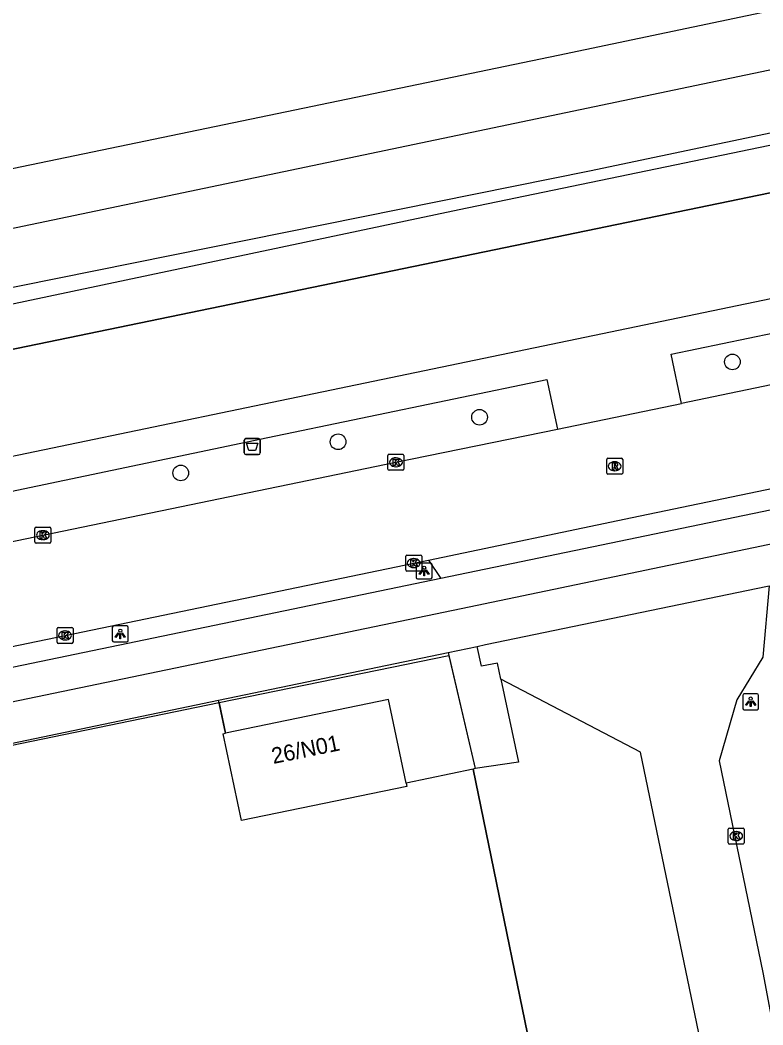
# Model space of a CAD drawing. Extents: x 164494 to 166241, y 382475 to 384494.
# Drawn here: x 164884.7 to 164931.2, y 384302.2 to 384365.1 of the extents above; entities that cross this region are included whole.
import ezdxf

# ---------------------------------------------------------------- set-up
doc = ezdxf.new("R2010")
doc.units = 0
for name, color, linetype in [('IMGEO_Afvalbak', 7, 'Continuous'), ('IMGEO_Boom', 7, 'Continuous'), ('IMGEO_Fietspad_open', 7, 'Continuous'), ('IMGEO_Greppel_droge_sloot', 7, 'Continuous'), ('IMGEO_Groenvoorziening', 7, 'Continuous'), ('IMGEO_Hek', 7, 'Continuous'), ('IMGEO_Kolk', 7, 'Continuous'), ('IMGEO_Lichtpunt', 7, 'Continuous'), ('IMGEO_Pand', 7, 'Continuous'), ('IMGEO_Pand_nummerreeks', 7, 'Continuous'), ('IMGEO_Rijbaan_lokaal_open', 7, 'Continuous'), ('IMGEO_Rioolput', 7, 'Continuous'), ('IMGEO_Spoor', 7, 'Continuous'), ('IMGEO_Spoorbaan_halfverhard', 7, 'Continuous'), ('IMGEO_Voetpad_open', 7, 'Continuous')]:
    doc.layers.add(name, color=color, linetype=linetype)

msp = doc.modelspace()

# ---------------------------------------------------------------- linework, layer by layer
at = {"layer": 'IMGEO_Afvalbak'}
for p, q in [((164898.756, 384338.007), (164898.756, 384338.807)), ((164898.756, 384338.807), (164898.756, 384338.007)), ((164898.856, 384338.907), (164899.646, 384338.907)), ((164899.646, 384338.907), (164898.856, 384338.907)), ((164899.746, 384338.807), (164899.746, 384338.007)), ((164899.746, 384338.007), (164899.746, 384338.807)), ((164899.646, 384337.907), (164898.856, 384337.907)), ((164898.856, 384337.907), (164899.646, 384337.907))]:
    msp.add_line(p, q, dxfattribs=at)
msp.add_lwpolyline([(164898.899, 384338.621), (164899.603, 384338.621), (164899.454, 384338.151), (164899.048, 384338.151), (164898.899, 384338.621)], dxfattribs=at)
for centre, start, end in [((164898.856, 384338.807), 90, 180), ((164898.856, 384338.807), 90, 180), ((164899.646, 384338.807), 0, 90), ((164899.646, 384338.807), 360, 90), ((164898.856, 384338.007), 180, 270), ((164898.856, 384338.007), 180, 270), ((164899.646, 384338.007), 270, 0), ((164899.646, 384338.007), 270, 0)]:
    msp.add_arc(centre, 0.1, start, end, dxfattribs=at)
at = {"layer": 'IMGEO_Boom'}
for centre in [(164929.289, 384343.703), (164913.47, 384340.242), (164904.622, 384338.703), (164894.777, 384336.754)]:
    msp.add_circle(centre, 0.489, dxfattribs=at)
at = {"layer": 'IMGEO_Fietspad_open'}
for points in [[(164926.103, 384341.106), (164925.461, 384344.192), (164936.708, 384346.52), (164998.737, 384359.434), (165044.842, 384369.066), (165078.417, 384376.067), (165103.145, 384381.247)], [(165123.59, 384372.323), (165118.614, 384371.278), (165101.155, 384367.679), (165052.181, 384357.436), (165001.876, 384346.919), (164996.584, 384345.814), (164978.743, 384342.085), (164958.923, 384337.938), (164932.507, 384332.46), (164912.329, 384328.255), (164868.92, 384319.253), (164838.611, 384312.969), (164833.08, 384311.822), (164809.925, 384307.04), (164802.068, 384305.407)], [(164984.803, 384358.696), (164934.915, 384348.321), (164898.89, 384340.836), (164875.602, 384335.981), (164845.275, 384329.624), (164797.88, 384319.828), (164794.806, 384319.188)], [(164795.6, 384317.184), (164798.561, 384317.801), (164845.552, 384327.536), (164876.06, 384333.902), (164900.22, 384338.981), (164917.673, 384342.602), (164918.341, 384339.504)], [(164911.059, 384330.145), (164868.55, 384321.331), (164832.678, 384313.85)]]:
    msp.add_lwpolyline(points, dxfattribs=at)
at = {"layer": 'IMGEO_Greppel_droge_sloot'}
for points in [[(165104.993, 384388.454), (165106.065, 384389.82), (165106.003, 384390.697), (165105.583, 384391.703), (165104.253, 384391.797), (165094.853, 384389.829), (165092.786, 384389.521), (165090.64, 384389.08), (165088.711, 384388.988), (165086.738, 384389.38), (165085.335, 384389.341), (165083.775, 384389.121), (165040.998, 384380.02), (165000.91, 384371.603), (164912.198, 384353.222), (164815.807, 384332.872), (164812.064, 384331.961), (164811.065, 384331.621), (164810.561, 384331.362), (164810.234, 384331.045), (164809.929, 384330.437), (164809.818, 384329.948), (164809.989, 384329.284), (164810.161, 384329.041)], [(164983.603, 384364.664), (164950.027, 384358.074), (164862.281, 384339.951), (164810.161, 384329.041)]]:
    msp.add_lwpolyline(points, dxfattribs=at)
at = {"layer": 'IMGEO_Groenvoorziening'}
msp.add_lwpolyline([(164930.87, 384284.21), (164924.878, 384283.015), (164922.096, 384296.28), (164917.769, 384295.38), (164913.081, 384318.227)], dxfattribs=at)
at = {"layer": 'IMGEO_Hek'}
for points in [[(164792.371, 384325.328), (164793.82, 384325.659), (164799.547, 384326.819), (164862.281, 384339.951), (164950.027, 384358.074), (164999.896, 384367.862), (165017.437, 384370.613), (165038.566, 384374.957), (165060.537, 384379.313), (165104.993, 384388.454), (165107.365, 384388.949), (165107.179, 384392.936), (165107.536, 384394.767)], [(164911.555, 384325.324), (164897.184, 384322.369)], [(164911.555, 384325.324), (164913.199, 384318.262)], [(164897.184, 384322.369), (164884.739, 384319.811), (164842.119, 384310.96), (164840.566, 384310.552)], [(164897.184, 384322.369), (164897.584, 384320.476)], [(164913.081, 384318.227), (164908.88, 384317.354)], [(164913.199, 384318.262), (164913.081, 384318.227)], [(164913.081, 384318.227), (164917.769, 384295.38)]]:
    msp.add_lwpolyline(points, dxfattribs=at)
at = {"layer": 'IMGEO_Kolk'}
for p, q in [((164907.741, 384336.994), (164907.741, 384337.846)), ((164907.816, 384337.92), (164908.668, 384337.92)), ((164908.229, 384337.7), (164908.254, 384337.7)), ((164908.742, 384337.846), (164908.742, 384336.994)), ((164908.252, 384337.14), (164908.227, 384337.14)), ((164908.668, 384336.92), (164907.816, 384336.92)), ((164885.654, 384332.436), (164885.654, 384333.288)), ((164885.729, 384333.362), (164886.581, 384333.362)), ((164886.655, 384333.288), (164886.655, 384332.436)), ((164886.142, 384333.142), (164886.167, 384333.142)), ((164886.581, 384332.362), (164885.729, 384332.362)), ((164886.165, 384332.582), (164886.14, 384332.582)), ((164908.852, 384330.69), (164908.852, 384331.542)), ((164908.927, 384331.616), (164909.779, 384331.616)), ((164909.853, 384331.542), (164909.853, 384330.69)), ((164909.363, 384330.836), (164909.338, 384330.836)), ((164909.34, 384331.396), (164909.365, 384331.396)), ((164909.779, 384330.616), (164908.927, 384330.616)), ((164887.038, 384326.164), (164887.038, 384327.016)), ((164887.113, 384327.09), (164887.965, 384327.09)), ((164888.039, 384327.016), (164888.039, 384326.164)), ((164887.526, 384326.87), (164887.551, 384326.87)), ((164887.965, 384326.09), (164887.113, 384326.09)), ((164887.549, 384326.31), (164887.524, 384326.31)), ((164929.029, 384313.618), (164929.029, 384314.47)), ((164929.104, 384314.544), (164929.956, 384314.544)), ((164930.03, 384314.47), (164930.03, 384313.618)), ((164929.517, 384314.324), (164929.542, 384314.324)), ((164929.956, 384313.544), (164929.104, 384313.544)), ((164929.54, 384313.764), (164929.515, 384313.764))]:
    msp.add_line(p, q, dxfattribs=at)
for points in [[(164907.741, 384336.994), (164907.741, 384337.846)], [(164907.816, 384337.92), (164908.668, 384337.92)], [(164908.742, 384337.846), (164908.742, 384336.994)], [(164908.062, 384337.62), (164908.185, 384337.62), (164908.185, 384337.469), (164908.315, 384337.62), (164908.479, 384337.62), (164908.333, 384337.469), (164908.486, 384337.22), (164908.334, 384337.22), (164908.249, 384337.384), (164908.185, 384337.317), (164908.185, 384337.22), (164908.062, 384337.22), (164908.062, 384337.62)], [(164908.668, 384336.92), (164907.816, 384336.92)], [(164885.654, 384332.436), (164885.654, 384333.288)], [(164885.729, 384333.362), (164886.581, 384333.362)], [(164886.655, 384333.288), (164886.655, 384332.436)], [(164885.975, 384333.062), (164886.098, 384333.062), (164886.098, 384332.911), (164886.228, 384333.062), (164886.392, 384333.062), (164886.246, 384332.911), (164886.399, 384332.662), (164886.247, 384332.662), (164886.162, 384332.826), (164886.098, 384332.759), (164886.098, 384332.662), (164885.975, 384332.662), (164885.975, 384333.062)], [(164886.581, 384332.362), (164885.729, 384332.362)], [(164908.852, 384330.69), (164908.852, 384331.542)], [(164908.927, 384331.616), (164909.779, 384331.616)], [(164909.853, 384331.542), (164909.853, 384330.69)], [(164909.173, 384331.316), (164909.296, 384331.316), (164909.296, 384331.165), (164909.426, 384331.316), (164909.59, 384331.316), (164909.444, 384331.165), (164909.597, 384330.916), (164909.445, 384330.916), (164909.36, 384331.08), (164909.296, 384331.013), (164909.296, 384330.916), (164909.173, 384330.916), (164909.173, 384331.316)], [(164909.779, 384330.616), (164908.927, 384330.616)], [(164887.038, 384326.164), (164887.038, 384327.016)], [(164887.113, 384327.09), (164887.965, 384327.09)], [(164888.039, 384327.016), (164888.039, 384326.164)], [(164887.359, 384326.79), (164887.482, 384326.79), (164887.482, 384326.639), (164887.612, 384326.79), (164887.776, 384326.79), (164887.63, 384326.639), (164887.783, 384326.39), (164887.631, 384326.39), (164887.546, 384326.554), (164887.482, 384326.487), (164887.482, 384326.39), (164887.359, 384326.39), (164887.359, 384326.79)], [(164887.965, 384326.09), (164887.113, 384326.09)], [(164929.029, 384313.618), (164929.029, 384314.47)], [(164929.104, 384314.544), (164929.956, 384314.544)], [(164930.03, 384314.47), (164930.03, 384313.618)], [(164929.35, 384314.244), (164929.473, 384314.244), (164929.473, 384314.093), (164929.603, 384314.244), (164929.767, 384314.244), (164929.621, 384314.093), (164929.774, 384313.844), (164929.622, 384313.844), (164929.537, 384314.008), (164929.473, 384313.941), (164929.473, 384313.844), (164929.35, 384313.844), (164929.35, 384314.244)], [(164929.956, 384313.544), (164929.104, 384313.544)]]:
    msp.add_lwpolyline(points, dxfattribs=at)
for centre, start, end in [((164907.818, 384337.844), 91.55205, 178.44795), ((164907.818, 384337.844), 91.55205, 178.44795), ((164908.666, 384337.844), 1.55205, 88.44795), ((164908.666, 384337.844), 1.55205, 88.44795), ((164907.818, 384336.996), 181.55205, 268.44795), ((164907.818, 384336.996), 181.55205, 268.44795), ((164908.666, 384336.996), 271.55205, 358.44795), ((164908.666, 384336.996), 271.55205, 358.44795), ((164885.731, 384333.286), 91.55205, 178.44795), ((164885.731, 384333.286), 91.55205, 178.44795), ((164886.579, 384333.286), 1.55205, 88.44795), ((164886.579, 384333.286), 1.55205, 88.44795), ((164885.731, 384332.438), 181.55205, 268.44795), ((164885.731, 384332.438), 181.55205, 268.44795), ((164886.579, 384332.438), 271.55205, 358.44795), ((164886.579, 384332.438), 271.55205, 358.44795), ((164908.929, 384331.54), 91.55205, 178.44795), ((164908.929, 384331.54), 91.55205, 178.44795), ((164909.777, 384331.54), 1.55205, 88.44795), ((164909.777, 384331.54), 1.55205, 88.44795), ((164908.929, 384330.692), 181.55205, 268.44795), ((164908.929, 384330.692), 181.55205, 268.44795), ((164909.777, 384330.692), 271.55205, 358.44795), ((164909.777, 384330.692), 271.55205, 358.44795), ((164887.115, 384327.014), 91.55205, 178.44795), ((164887.115, 384327.014), 91.55205, 178.44795), ((164887.963, 384327.014), 1.55205, 88.44795), ((164887.963, 384327.014), 1.55205, 88.44795), ((164887.115, 384326.166), 181.55205, 268.44795), ((164887.115, 384326.166), 181.55205, 268.44795), ((164887.963, 384326.166), 271.55205, 358.44795), ((164887.963, 384326.166), 271.55205, 358.44795), ((164929.106, 384314.468), 91.55205, 178.44795), ((164929.106, 384314.468), 91.55205, 178.44795), ((164929.954, 384314.468), 1.55205, 88.44795), ((164929.954, 384314.468), 1.55205, 88.44795), ((164929.106, 384313.62), 181.55205, 268.44795), ((164929.106, 384313.62), 181.55205, 268.44795), ((164929.954, 384313.62), 271.55205, 358.44795), ((164929.954, 384313.62), 271.55205, 358.44795)]:
    msp.add_arc(centre, 0.0765, start, end, dxfattribs=at)
for centre, major_axis, ratio, start_param, end_param in [((164908.228, 384337.42), (-0.387, 0.002), 0.722429, 4.712389, 7.853982), ((164908.253, 384337.42), (-0.39, 0.002), 0.717154, 1.570796, 4.712389), ((164886.141, 384332.862), (-0.387, 0.002), 0.722429, 4.712389, 7.853982), ((164886.166, 384332.862), (-0.39, 0.002), 0.717154, 1.570796, 4.712389), ((164909.339, 384331.116), (-0.387, 0.002), 0.722429, 4.712389, 7.853982), ((164909.364, 384331.116), (-0.39, 0.002), 0.717154, 1.570796, 4.712389), ((164887.525, 384326.59), (-0.387, 0.002), 0.722429, 4.712389, 7.853982), ((164887.55, 384326.59), (-0.39, 0.002), 0.717154, 1.570796, 4.712389), ((164929.516, 384314.044), (-0.387, 0.002), 0.722429, 4.712389, 7.853982), ((164929.541, 384314.044), (-0.39, 0.002), 0.717154, 1.570796, 4.712389)]:
    msp.add_ellipse(centre, major_axis=major_axis, ratio=ratio, start_param=start_param, end_param=end_param, dxfattribs=at)
at = {"layer": 'IMGEO_Lichtpunt'}
for p, q in [((164909.505, 384331.027), (164909.505, 384330.22)), ((164909.505, 384331.027), (164909.505, 384330.22)), ((164910.407, 384331.122), (164909.599, 384331.122)), ((164910.407, 384331.122), (164909.599, 384331.122)), ((164910.501, 384330.22), (164910.501, 384331.027)), ((164910.501, 384330.22), (164910.501, 384331.027)), ((164909.599, 384330.126), (164910.407, 384330.126)), ((164909.599, 384330.126), (164910.407, 384330.126)), ((164890.497, 384327.09), (164890.497, 384326.283)), ((164890.497, 384327.09), (164890.497, 384326.283)), ((164891.399, 384327.185), (164890.591, 384327.185)), ((164891.399, 384327.185), (164890.591, 384327.185)), ((164891.493, 384326.283), (164891.493, 384327.09)), ((164891.493, 384326.283), (164891.493, 384327.09)), ((164890.591, 384326.189), (164891.399, 384326.189)), ((164890.591, 384326.189), (164891.399, 384326.189)), ((164929.935, 384322.843), (164929.935, 384322.036)), ((164929.935, 384322.843), (164929.935, 384322.036)), ((164930.837, 384322.938), (164930.029, 384322.938)), ((164930.837, 384322.938), (164930.029, 384322.938)), ((164930.931, 384322.036), (164930.931, 384322.843)), ((164930.931, 384322.036), (164930.931, 384322.843)), ((164930.029, 384321.942), (164930.837, 384321.942)), ((164930.029, 384321.942), (164930.837, 384321.942))]:
    msp.add_line(p, q, dxfattribs=at)
for points in [[(164909.879, 384330.691), (164909.918, 384330.663), (164909.73, 384330.401), (164909.692, 384330.428), (164909.879, 384330.691)], [(164909.981, 384330.643), (164910.028, 384330.643), (164910.028, 384330.321), (164909.981, 384330.321), (164909.981, 384330.643)], [(164910.091, 384330.663), (164910.129, 384330.69), (164910.316, 384330.428), (164910.277, 384330.4), (164910.091, 384330.663)], [(164890.871, 384326.754), (164890.91, 384326.726), (164890.722, 384326.464), (164890.684, 384326.491), (164890.871, 384326.754)], [(164890.973, 384326.706), (164891.02, 384326.706), (164891.02, 384326.384), (164890.973, 384326.384), (164890.973, 384326.706)], [(164891.083, 384326.726), (164891.121, 384326.753), (164891.308, 384326.491), (164891.269, 384326.463), (164891.083, 384326.726)], [(164930.309, 384322.507), (164930.348, 384322.479), (164930.16, 384322.217), (164930.122, 384322.244), (164930.309, 384322.507)], [(164930.411, 384322.459), (164930.458, 384322.459), (164930.458, 384322.137), (164930.411, 384322.137), (164930.411, 384322.459)], [(164930.521, 384322.479), (164930.559, 384322.506), (164930.746, 384322.244), (164930.707, 384322.216), (164930.521, 384322.479)]]:
    msp.add_lwpolyline(points, dxfattribs=at)
for centre in [(164910.004, 384330.825), (164890.996, 384326.888), (164930.434, 384322.641)]:
    msp.add_circle(centre, 0.0994, dxfattribs=at)
for centre, start, end in [((164909.599, 384331.027), 90, 180), ((164909.599, 384331.027), 90, 180), ((164910.407, 384331.027), 0, 90), ((164910.407, 384331.027), 0, 90), ((164909.599, 384330.22), 180, 270), ((164909.599, 384330.22), 180, 270), ((164910.407, 384330.22), 270, 0), ((164910.407, 384330.22), 270, 360), ((164890.591, 384327.09), 90, 180), ((164890.591, 384327.09), 90, 180), ((164891.399, 384327.09), 0, 90), ((164891.399, 384327.09), 0, 90), ((164890.591, 384326.283), 180, 270), ((164890.591, 384326.283), 180, 270), ((164891.399, 384326.283), 270, 0), ((164891.399, 384326.283), 270, 360), ((164930.029, 384322.843), 90, 180), ((164930.029, 384322.843), 90, 180), ((164930.837, 384322.843), 0, 90), ((164930.837, 384322.843), 0, 90), ((164930.029, 384322.036), 180, 270), ((164930.029, 384322.036), 180, 270), ((164930.837, 384322.036), 270, 0), ((164930.837, 384322.036), 270, 360)]:
    msp.add_arc(centre, 0.0946, start, end, dxfattribs=at)
at = {"layer": 'IMGEO_Pand'}
for points in [[(164908.88, 384317.354), (164907.784, 384322.582), (164897.584, 384320.476)], [(164908.88, 384317.354), (164908.923, 384317.148), (164898.571, 384315.011), (164897.432, 384320.445), (164897.584, 384320.476)]]:
    msp.add_lwpolyline(points, dxfattribs=at)
at = {"layer": 'IMGEO_Rijbaan_lokaal_open'}
for points in [[(165103.841, 384378.298), (165103.18, 384378.131), (165082.552, 384373.828), (165059.459, 384368.999), (165037.346, 384364.383), (165015.253, 384359.737), (164994.137, 384355.385), (164980.37, 384352.43), (164954.306, 384347.035), (164933.216, 384342.574), (164926.103, 384341.106)], [(164918.341, 384339.504), (164926.103, 384341.106)], [(164796.746, 384314.295), (164800.79, 384315.134), (164823.887, 384319.91), (164845.934, 384324.502), (164865.073, 384328.486), (164886.155, 384332.862), (164908.242, 384337.42), (164918.341, 384339.504)], [(164910.275, 384331.309), (164923.017, 384333.971), (164933.937, 384336.234)], [(164933.359, 384334.783), (164911.059, 384330.145)], [(164832.428, 384315.154), (164847.04, 384318.189), (164866.083, 384322.138), (164887.539, 384326.59), (164909.353, 384331.116), (164910.275, 384331.309)], [(164910.275, 384331.309), (164911.059, 384330.145)], [(164913.321, 384325.907), (164913.849, 384326.017), (164931.494, 384329.683), (164931.595, 384329.704)], [(164931.595, 384329.704), (164931.189, 384325.235), (164929.571, 384322.569), (164928.461, 384318.744), (164931.192, 384305.516), (164935.029, 384285.096), (164930.87, 384284.21)], [(164914.805, 384323.848), (164914.593, 384324.849), (164913.602, 384324.675), (164913.321, 384325.907)], [(164928.077, 384297.39), (164923.539, 384319.297), (164914.805, 384323.848)]]:
    msp.add_lwpolyline(points, dxfattribs=at)
at = {"layer": 'IMGEO_Rioolput'}
for p, q in [((164921.424, 384336.748), (164921.424, 384337.6)), ((164921.499, 384337.674), (164922.351, 384337.674)), ((164921.912, 384337.454), (164921.937, 384337.454)), ((164922.425, 384337.6), (164922.425, 384336.748)), ((164922.351, 384336.674), (164921.499, 384336.674)), ((164921.935, 384336.894), (164921.91, 384336.894))]:
    msp.add_line(p, q, dxfattribs=at)
for points in [[(164921.424, 384336.748), (164921.424, 384337.6)], [(164921.499, 384337.674), (164922.351, 384337.674)], [(164922.013, 384337.372), (164921.761, 384337.374), (164921.761, 384336.974)], [(164921.761, 384336.974), (164921.885, 384336.974), (164921.885, 384337.136), (164921.896, 384337.136)], [(164921.939, 384337.293), (164921.885, 384337.293), (164921.885, 384337.212)], [(164921.885, 384337.212), (164921.937, 384337.212)], [(164921.943, 384337.107), (164922.014, 384336.974), (164922.154, 384336.974), (164922.089, 384337.1)], [(164922.425, 384337.6), (164922.425, 384336.748)], [(164922.351, 384336.674), (164921.499, 384336.674)]]:
    msp.add_lwpolyline(points, dxfattribs=at)
for centre, radius, start, end in [((164921.501, 384337.598), 0.0765, 91.55205, 178.44795), ((164921.501, 384337.598), 0.0765, 91.55205, 178.44795), ((164921.895, 384337.083), 0.0533, 26.02933, 88.69889), ((164921.921, 384337.401), 0.19, 274.7715, 282.96867), ((164921.945, 384337.197), 0.0964, 77.00612, 93.18647), ((164921.959, 384337.254), 0.0378, 276.66336, 79.67722), ((164922.012, 384337.262), 0.109, 350.36119, 89.41601), ((164922.01, 384337.262), 0.112, 277.58423, 350.98172), ((164921.994, 384337.047), 0.108, 29.51342, 73.79051), ((164922.349, 384337.598), 0.0765, 1.55205, 88.44795), ((164922.349, 384337.598), 0.0765, 1.55205, 88.44795), ((164921.501, 384336.75), 0.0765, 181.55205, 268.44795), ((164921.501, 384336.75), 0.0765, 181.55205, 268.44795), ((164922.349, 384336.75), 0.0765, 271.55205, 358.44795), ((164922.349, 384336.75), 0.0765, 271.55205, 358.44795)]:
    msp.add_arc(centre, radius, start, end, dxfattribs=at)
for centre, major_axis, ratio, start_param, end_param in [((164921.911, 384337.174), (-0.387, 0.002), 0.722429, 4.712389, 7.853982), ((164921.936, 384337.174), (-0.39, 0.002), 0.717154, 1.570796, 4.712389)]:
    msp.add_ellipse(centre, major_axis=major_axis, ratio=ratio, start_param=start_param, end_param=end_param, dxfattribs=at)
at = {"layer": 'IMGEO_Spoor'}
for points in [[(165534.642, 384491.339), (165527.155, 384489.842), (165498.336, 384483.749), (165300.848, 384442.555), (165180.102, 384417.538), (165154.253, 384412.052), (165058.779, 384392.205), (165020.911, 384384.156), (164953.473, 384370.243), (164918.38, 384362.867), (164827.656, 384344.031), (164796.154, 384337.413), (164788.231, 384335.773)], [(165535.404, 384487.554), (165347.592, 384448.533), (165284.368, 384435.3), (165189.312, 384415.622), (165019.715, 384380.308), (164986.051, 384373.23), (164945.984, 384364.945), (164850.572, 384344.992), (164797.73, 384334.115), (164789.572, 384332.389)]]:
    msp.add_lwpolyline(points, dxfattribs=at)
at = {"layer": 'IMGEO_Spoorbaan_halfverhard'}
msp.add_lwpolyline([(164796.468, 384328.762), (164809.794, 384332.027), (164812.313, 384333.001), (164815.919, 384334.01), (164826.252, 384336.209), (164847.742, 384340.431), (164860.86, 384343.215), (164877.535, 384347.017), (164920.34, 384355.646), (164963.792, 384364.777), (164989.47, 384369.926), (164993.61, 384371.368), (165009.016, 384374.65), (165030.52, 384378.991), (165047.947, 384382.37), (165057.819, 384384.438), (165069.605, 384387.142), (165081.406, 384389.702), (165082.707, 384390.536), (165089.022, 384391.879)], dxfattribs=at)
at = {"layer": 'IMGEO_Voetpad_open'}
for points in [[(164911.507, 384325.529), (164913.321, 384325.907)], [(164897.149, 384322.536), (164911.507, 384325.529)], [(164911.507, 384325.529), (164913.199, 384318.262)], [(164914.805, 384323.848), (164915.899, 384318.672), (164913.199, 384318.262)], [(164801.347, 384302.69), (164802.345, 384302.907), (164810.439, 384304.577), (164815.303, 384305.586), (164837.573, 384310.195), (164869.34, 384316.739), (164897.149, 384322.536)], [(164897.584, 384320.476), (164897.149, 384322.536)], [(164913.081, 384318.227), (164908.88, 384317.354)], [(164913.199, 384318.262), (164913.081, 384318.227)]]:
    msp.add_lwpolyline(points, dxfattribs=at)

# ---------------------------------------------------------------- texts
at = {"layer": 'IMGEO_Pand_nummerreeks'}
msp.add_text('26/N01', height=1, rotation=11.47062, dxfattribs=at).set_placement((164900.569, 384318.55))

doc.saveas('drawing.dxf')
